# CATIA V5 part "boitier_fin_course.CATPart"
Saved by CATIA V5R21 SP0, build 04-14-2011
Part number: boitier_fin_course
Bounding box of the stored display mesh (mm): x -5 to 6, y -12 to 25, z 0 to 8
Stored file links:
  C:\Users\zerma\Pictures\CAO\boitier_fin_course.CATPart
  C:\Users\zerma\Pictures\CAO\Ensemble fin de course.CATProduct
  C:\Users\zerma\Pictures\CAO\d2f-01l.CATPart
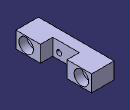
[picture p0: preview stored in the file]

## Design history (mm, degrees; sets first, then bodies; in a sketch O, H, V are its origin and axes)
Set1
  DatumCurve1: linked copy from another document
  Plane1: linked copy from another document
Body1 (main body)
  Sketch1 on xy-plane, origin (0, 0, 0), H (1, 0, 0), V (0, 1, 0)
    line L1 (0, 13) -> (6, 13)
    line L2 (6, 0) -> (0, 0)
    line L3 (0, 0) -> (0, 13)
    point P4 (0, 0)
    line L4 (6, 13) -> (6, 15)
    line L5 (6, 15) -> (-5, 15)
    line L6 (-5, 15) -> (-5, -2)
    line L7 (6, 0) -> (6, -2)
    line L8 (-5, -2) -> (6, -2)
    length L1 = 6
    length L3 = 13
    length L4 = 2
    length L7 = 2
    length L5 = 11
    length L8 = 11
    horizontal: L1 H, L2 H, L5 H, L8 H
    vertical: L3 V, L4 V, L6 V, L7 V
    coincidence: P4 O
  Pad1: profile Sketch1, direction (0, 0, 1), length 8
  Sketch2 on face of Pad1 from Sketch1.L3, origin (0, 0, 0), H (0, 1, 0), V (0, 0, 1)
    point P1 (0.9, 0)
    circle A1 centre (10.15, 3) radius 1.25
    circle A2 centre (3.15, 3) radius 1.25
    radius A1 = 1.25
    distance A1 A2 = 4.5
    radius A2 = 1.25
  Pocket1: profile Sketch2, direction (-1, 0, 0), length 5
  Sketch3 on face of Pad1 from Sketch1.L6, origin (-5, 0, 0), H (0, -1, 0), V (0, 0, 1)
    circle A1 centre (-3.15, 3) radius 2
    circle A2 centre (-10.15, 3) radius 2
    reference projected circle E1 centre (-3.15, 3) radius 1.25 from edge [face of Pad1 from Sketch1.L6 | face of Pocket1 from Sketch2.A2]
    reference projected circle E2 centre (-10.15, 3) radius 1.25 from edge [face of Pad1 from Sketch1.L6 | face of Pocket1 from Sketch2.A1]
    radius A1 = 2
    radius A2 = 2
    concentricity: A1 E1, A2 E2
  Pocket2: profile Sketch3, direction (1, 0, 0), length 2
  Sketch4 on face of Pad1 from Sketch1.L5, origin (0, 15, 0), H (-1, 0, 0), V (0, 0, 1)
    line L1 (-6, 8) -> (5, 8)
    line L2 (5, 8) -> (5, 0)
    line L3 (5, 0) -> (-6, 0)
    line L4 (-6, 0) -> (-6, 8)
    reference projected line E1 (5, 0) -> (5, 8) from edge [face of Pad1 from Sketch1.L6 | face of Pad1 from Sketch1.L5]
    reference projected line E2 (-6, 8) -> (5, 8) from edge [face of Pad1 from Sketch1.L5 | end face of Pad1]
    reference projected line E3 (-6, 0) -> (5, 0) from edge [start face of Pad1 | face of Pad1 from Sketch1.L5]
    length L1 = 11
    horizontal: L1 H, L3 H
    vertical: L2 V, L4 V
    coincidence: L2 E1, L1 E2, L3 E3
  Pad2: profile Sketch4, direction (0, 1, 0), length 10
  Sketch5 on face of Pad2, origin (6, 21.1157, 3.7317), H (0, 1, 0), V (0, 0, 1)
    point P1 (-1.1157, 0.2683)
    reference projected line E1 (3.8843, 4.2683) -> (3.8843, -3.7317) from edge [face of Pad2 | end face of Pad2]
    reference projected line E2 (-8.1157, 4.2683) -> (-6.1157, 4.2683) from edge [face of Pad2 | face of Pad2]
    distance P1 E1 = 5
    distance P1 E2 = 4
  Hole1: placed by Sketch5, at (6, 20, 4) direction (-1, 0, 0), diameter 4.3, through (limit type 6)
  Sketch6 on face of Pad2, origin (6, 23.3227, 5.8641), H (0, 1, 0), V (0, 0, 1)
    point P1 (-3.3227, -1.8641)
    reference projected circle E1 centre (-3.3227, -1.8641) radius 2.15 from edge [face of Pad2 | face of Hole1]
    concentricity: P1 E1
  Hole2: placed by Sketch6, at (6, 20, 4) direction (-1, 0, 0), diameter 7, depth 4
  Sketch7 on face of Pad1 from Sketch1.L8, origin (0, -2, 0), H (1, 0, 0), V (0, 0, 1)
    line L1 (-5, 8) -> (6, 8)
    line L2 (6, 8) -> (6, 0)
    line L3 (6, 0) -> (-5, 0)
    line L4 (-5, 0) -> (-5, 8)
    reference projected line E1 (-5, 8) -> (6, 8) from edge [face of Pad1 from Sketch1.L8 | face of Pad2]
    reference projected line E2 (-5, 0) -> (6, 0) from edge [face of Pad2 | face of Pad1 from Sketch1.L8]
    reference projected line E3 (-5, 0) -> (-5, 8) from edge [face of Pad1 from Sketch1.L8 | face of Pad2]
    length L1 = 11
    horizontal: L1 H, L3 H
    vertical: L2 V, L4 V
    coincidence: L1 E1, L3 E2, L4 E3
  Pad3: profile Sketch7, direction (0, -1, 0), length 10
  Sketch8 on face of Pad3, origin (6, -5.9988, 3.2638), H (0, 1, 0), V (0, 0, 1)
    point P1 (-1.0012, 0.7362)
    reference projected line E1 (-6.0012, -3.2638) -> (-6.0012, 4.7362) from edge [face of Pad3 | end face of Pad3]
    reference projected line E2 (3.9988, 4.7362) -> (5.9988, 4.7362) from edge [face of Pad3 | face of Pad3]
    distance P1 E1 = 5
    distance P1 E2 = 4
  Hole3: placed by Sketch8, at (6, -7, 4) direction (-1, 0, 0), diameter 7, depth 4
  Sketch9 on face of Pad3, origin (6, -2.2767, 5.876), H (0, 1, 0), V (0, 0, 1)
    point P1 (-4.7233, -1.876)
    reference projected circle E1 centre (-4.7233, -1.876) radius 3.5 from edge [face of Pad3 | face of Hole3]
    concentricity: P1 E1
  Hole4: placed by Sketch9, at (6, -7, 4) direction (-1, 0, 0), diameter 4.1, through (limit type 6)
  CLDGeom1 "Maillage.1"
